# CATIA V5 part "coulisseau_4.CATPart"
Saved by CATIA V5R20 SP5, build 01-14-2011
Part number: coulisseau_4
Bounding box of the stored display mesh (mm): x 0 to 10, y -5 to 5, z -15 to 15
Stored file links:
  E:\IAO_2010\iao\IAO_MMS_Groupe2\IAO_MMS_Groupe2\flafosse\Catia\IAO\coulisseau_4.CATPart
  E:\IAO_2010\iao\IAO_MMS_Groupe2\IAO_MMS_Groupe2\flafosse\Catia\IAO\coulisseau5.CATPart
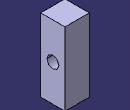
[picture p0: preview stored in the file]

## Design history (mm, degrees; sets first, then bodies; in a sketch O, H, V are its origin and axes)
Body1 (main body)
  Sketch1 on yz-plane, origin (0, 0, 0), H (0, 1, 0), V (0, 0, 1)
    line L1 (5, 15) -> (5, -15)
    line L2 (5, -15) -> (-5, -15)
    line L3 (-5, -15) -> (-5, 15)
    line L4 (-5, 15) -> (5, 15)
    circle A1 centre (0, 0) radius 2.5
    length L4 = 10
    radius A1 = 2.5
    length L1 = 30
    vertical: L1 V, L3 V
    horizontal: L2 H, L4 H
    equidistance: L1 L3 O, L2 L4 O
    perpendicularity: L4 L3
    parallelism: L4 L2
  Pad1: profile Sketch1, direction (1, 0, 0), length 10
  Point1: type Center, Curve edge [end face of Pad1 | face of Pad1 from Sketch1.A1]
